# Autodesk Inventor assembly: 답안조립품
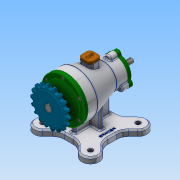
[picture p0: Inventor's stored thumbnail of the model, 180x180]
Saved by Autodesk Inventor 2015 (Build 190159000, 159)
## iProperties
Created: 2018-03
Part Number: 답안조립품
Document SubType Name: Assembly
Designer: SCD-A03
Author: SCD-A03
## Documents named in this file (15)
- C:\Users\SCD-A03\Documents\480307V1015\답안조립품.iam
- C:\Users\SCD-A03\Documents\480307V1015\본체.ipt
- C:\Users\SCD-A03\Documents\480307V1015\뒤커버.ipt
- C:\Users\SCD-A03\Documents\480307V1015\마개.ipt
- C:\Users\SCD-A03\Documents\480307V1015\베어링-6200.ipt
- C:\Users\SCD-A03\Documents\480307V1015\베어링-6203.ipt
- C:\Users\SCD-A03\Documents\480307V1015\볼트 M4 x 12.ipt
- 볼트 M4 x 12.ipt
- C:\Users\SCD-A03\Documents\480307V1015\스프로킷.ipt
- C:\Users\SCD-A03\Documents\480307V1015\앞커버.ipt
- C:\Users\SCD-A03\Documents\480307V1015\오일 실 10 20 7.ipt
- C:\Users\SCD-A03\Documents\480307V1015\오일 실 17 30 8.ipt
- C:\Users\SCD-A03\Documents\480307V1015\축.ipt
- C:\Users\SCD-A03\Documents\480307V1015\키 5 x 5.ipt
- 키 5 x 5.ipt
